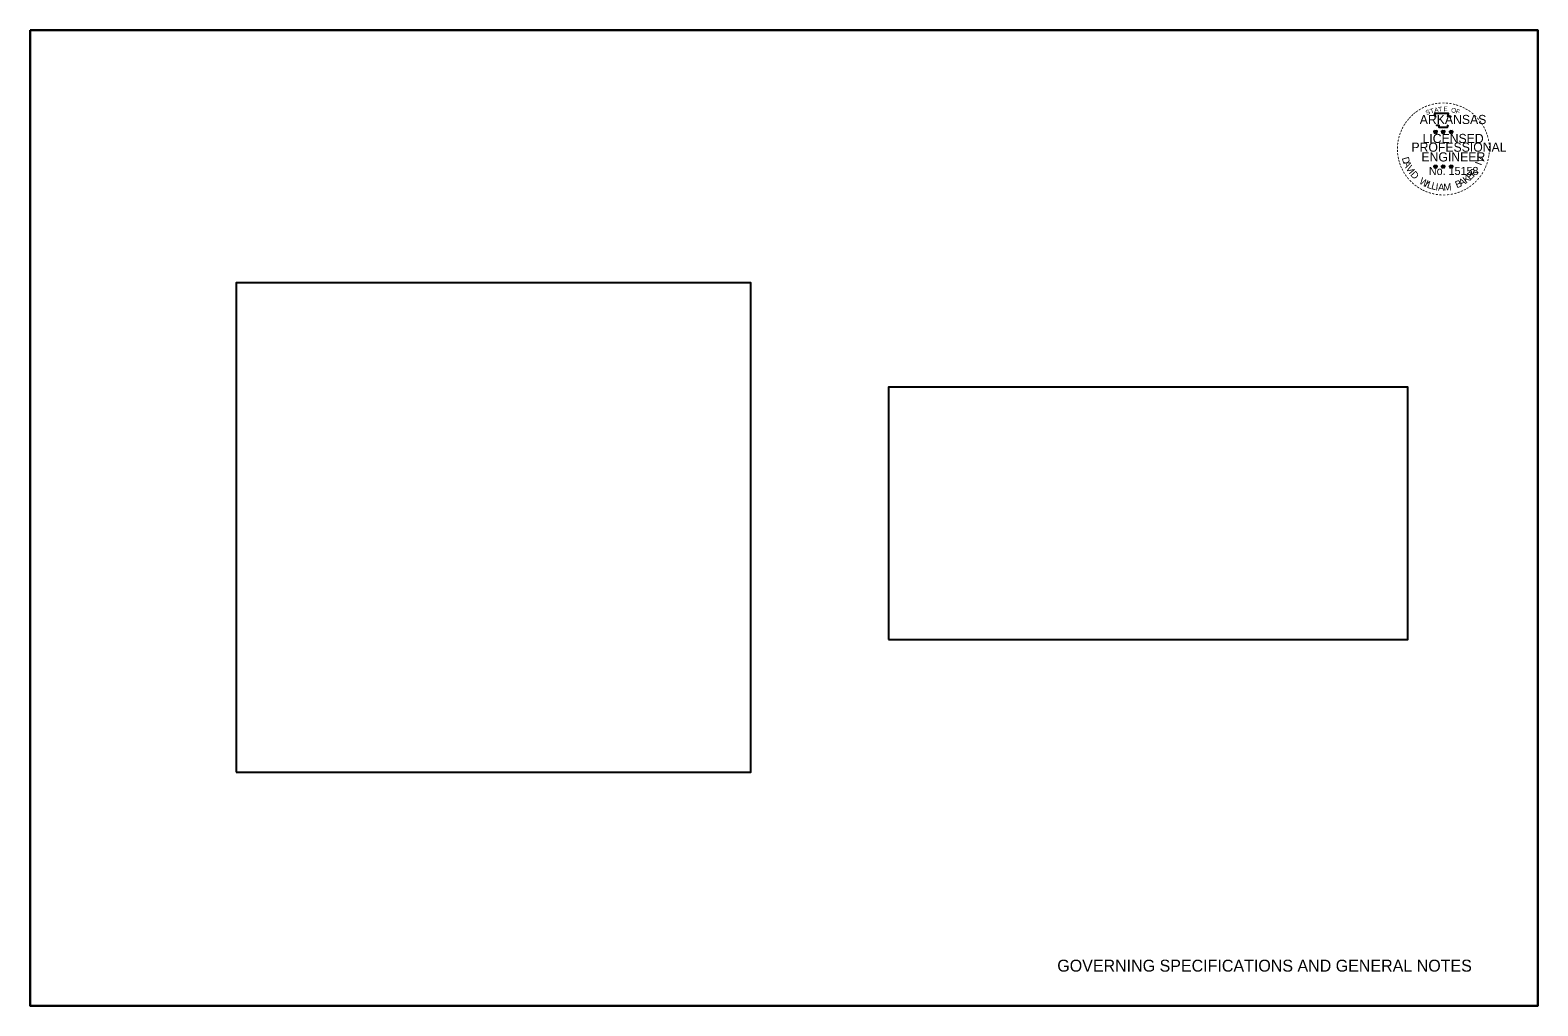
# Model space of a CAD drawing. Extents: x 28704 to 32542, y 50360 to 59122.
# Drawn here: x 28704 to 30404, y 55472 to 56572 of the extents above; entities that cross this region are included whole.
import ezdxf

# ---------------------------------------------------------------- set-up
doc = ezdxf.new("R2010")
doc.units = 0
for name, color, linetype in [('Default', 7, 'Continuous'), ('E_Existing ROW', 7, 'Continuous'), ('R_Border Prem', 7, 'Continuous')]:
    doc.layers.add(name, color=color, linetype=linetype)

msp = doc.modelspace()

# ---------------------------------------------------------------- linework, layer by layer
at = {"layer": 'Default'}
for points in [[(28704, 56572.4), (30404, 56572.4), (30404, 55472.4), (28704, 55472.4)], [(28704, 56572.4), (28704, 55472.4), (30404, 55472.4), (30404, 56572.4)], [(28936.2, 55735.9), (29516.5, 55735.9), (29516.5, 56287.6), (28936.2, 56287.6)], [(29671.6, 55885.4), (30257.3, 55885.4), (30257.3, 56169.8), (29671.6, 56169.8)]]:
    msp.add_lwpolyline(points, close=True, dxfattribs=at)
at = {"layer": 'R_Border Prem'}
for p, q in [((30286.8, 56458.3), (30288.6, 56457.7)), ((30286.8, 56458.3), (30288.1, 56458)), ((30286.8, 56458.3), (30288.1, 56457.6)), ((30287.5, 56456.2), (30288.6, 56457.7)), ((30287.5, 56456.2), (30288.2, 56457.4)), ((30287.5, 56456.2), (30288.6, 56457.3)), ((30288.6, 56459.6), (30288.4, 56458.3)), ((30288.6, 56457.7), (30288.6, 56459.6)), ((30288.6, 56459.6), (30288.9, 56458.3)), ((30290.4, 56458.3), (30288.6, 56457.7)), ((30289.7, 56456.2), (30288.6, 56457.7)), ((30289.7, 56456.2), (30288.6, 56457.3)), ((30290.4, 56458.3), (30288.9, 56458)), ((30289.7, 56456.2), (30289, 56457.7)), ((30290.4, 56458.3), (30289.4, 56457.7)), ((30295.4, 56458.3), (30297.2, 56457.7)), ((30295.4, 56458.3), (30296.8, 56458)), ((30295.4, 56458.3), (30296.7, 56457.6)), ((30296.1, 56456.2), (30297.2, 56457.7)), ((30296.1, 56456.2), (30296.8, 56457.4)), ((30296.1, 56456.2), (30297.2, 56457.3)), ((30297.2, 56459.6), (30297, 56458.3)), ((30297.2, 56457.7), (30297.2, 56459.6)), ((30297.2, 56459.6), (30297.5, 56458.3)), ((30299, 56458.3), (30297.2, 56457.7)), ((30298.3, 56456.2), (30297.2, 56457.7)), ((30298.3, 56456.2), (30297.2, 56457.3)), ((30299, 56458.3), (30297.6, 56458)), ((30298.3, 56456.2), (30297.6, 56457.7)), ((30299, 56458.3), (30298, 56457.7)), ((30304.5, 56458.2), (30306.3, 56457.6)), ((30304.5, 56458.2), (30305.8, 56458)), ((30304.5, 56458.2), (30305.8, 56457.6)), ((30305.2, 56456.1), (30306.3, 56457.6)), ((30305.2, 56456.1), (30305.9, 56457.4)), ((30305.2, 56456.1), (30306.3, 56457.2)), ((30306.3, 56459.5), (30306.1, 56458.2)), ((30306.3, 56457.6), (30306.3, 56459.5)), ((30306.3, 56459.5), (30306.6, 56458.2)), ((30308.1, 56458.2), (30306.3, 56457.6)), ((30307.4, 56456.1), (30306.3, 56457.6)), ((30307.4, 56456.1), (30306.3, 56457.2)), ((30308.1, 56458.2), (30306.7, 56458)), ((30307.4, 56456.1), (30306.7, 56457.6)), ((30308.1, 56458.2), (30307.1, 56457.7)), ((30286.8, 56419.2), (30288.6, 56418.6)), ((30286.8, 56419.2), (30288.1, 56419)), ((30286.8, 56419.2), (30288, 56418.6)), ((30287.5, 56417.1), (30288.6, 56418.6)), ((30287.5, 56417.1), (30288.2, 56418.4)), ((30287.5, 56417.1), (30288.6, 56418.2)), ((30288.6, 56420.5), (30288.4, 56419.2)), ((30288.6, 56418.6), (30288.6, 56420.5)), ((30288.6, 56420.5), (30288.9, 56419.2)), ((30290.4, 56419.2), (30288.6, 56418.6)), ((30289.7, 56417.1), (30288.6, 56418.6)), ((30289.7, 56417.1), (30288.6, 56418.2)), ((30290.4, 56419.2), (30288.9, 56419)), ((30289.7, 56417.1), (30289, 56418.6)), ((30290.4, 56419.2), (30289.4, 56418.7)), ((30295.4, 56419.2), (30297.2, 56418.6)), ((30295.4, 56419.2), (30296.7, 56419)), ((30295.4, 56419.2), (30296.6, 56418.6)), ((30296.1, 56417.1), (30297.2, 56418.6)), ((30296.1, 56417.1), (30296.8, 56418.4)), ((30296.1, 56417.1), (30297.2, 56418.2)), ((30297.2, 56420.5), (30297, 56419.2)), ((30297.2, 56418.6), (30297.2, 56420.5)), ((30297.2, 56420.5), (30297.5, 56419.2)), ((30299, 56419.2), (30297.2, 56418.6)), ((30298.3, 56417.1), (30297.2, 56418.6)), ((30298.3, 56417.1), (30297.2, 56418.2)), ((30299, 56419.2), (30297.5, 56419)), ((30298.3, 56417.1), (30297.6, 56418.6)), ((30299, 56419.2), (30298, 56418.7)), ((30304.5, 56419.2), (30306.3, 56418.6)), ((30304.5, 56419.2), (30305.8, 56418.9)), ((30304.5, 56419.2), (30305.8, 56418.5)), ((30305.2, 56417.1), (30306.3, 56418.6)), ((30305.2, 56417.1), (30305.9, 56418.3)), ((30305.2, 56417.1), (30306.3, 56418.2)), ((30306.3, 56420.5), (30306.1, 56419.2)), ((30306.3, 56418.6), (30306.3, 56420.5)), ((30306.3, 56420.5), (30306.6, 56419.2)), ((30308.1, 56419.2), (30306.3, 56418.6)), ((30307.4, 56417.1), (30306.3, 56418.6)), ((30307.4, 56417.1), (30306.3, 56418.2)), ((30308.1, 56419.2), (30306.6, 56418.9)), ((30307.4, 56417.1), (30306.7, 56418.6)), ((30308.1, 56419.2), (30307.1, 56418.6))]:
    msp.add_line(p, q, dxfattribs=at)
for points in [[(30287, 56478.3), (30288.4, 56474)], [(30305.2, 56473.5), (30305.9, 56475), (30302.4, 56474.9), (30303.1, 56478.3), (30287, 56478.3)], [(30288.6, 56459.6), (30289.7, 56456.2), (30286.8, 56458.3), (30290.4, 56458.3), (30287.5, 56456.2), (30288.6, 56459.6)], [(30289.6, 56465.8), (30289.6, 56465.3), (30292.5, 56465.2), (30292.2, 56462.8), (30301.9, 56462.8), (30302.9, 56465.5)], [(30297.2, 56459.6), (30298.3, 56456.2), (30295.4, 56458.3), (30299, 56458.3), (30296.1, 56456.2), (30297.2, 56459.6)], [(30306.3, 56459.5), (30307.4, 56456.1), (30304.5, 56458.2), (30308.1, 56458.2), (30305.2, 56456.1), (30306.3, 56459.5)], [(30288.6, 56420.5), (30289.7, 56417.1), (30286.8, 56419.2), (30290.4, 56419.2), (30287.5, 56417.1), (30288.6, 56420.5)], [(30297.2, 56420.5), (30298.3, 56417.1), (30295.4, 56419.2), (30299, 56419.2), (30296.1, 56417.1), (30297.2, 56420.5)], [(30306.3, 56420.5), (30307.4, 56417.1), (30304.5, 56419.2), (30308.1, 56419.2), (30305.2, 56417.1), (30306.3, 56420.5)]]:
    msp.add_lwpolyline(points, dxfattribs=at)
for centre, radius in [((30288.6, 56457.7), 0.888), ((30288.6, 56457.7), 0.745), ((30288.6, 56457.7), 0.597), ((30288.6, 56457.7), 0.511), ((30288.6, 56457.7), 0.385), ((30288.6, 56457.7), 0.255), ((30288.6, 56457.7), 0.153), ((30297.2, 56457.7), 0.888), ((30297.2, 56457.7), 0.745), ((30297.2, 56457.7), 0.597), ((30297.2, 56457.7), 0.511), ((30297.2, 56457.7), 0.385), ((30297.2, 56457.7), 0.255), ((30297.2, 56457.7), 0.153), ((30306.3, 56457.6), 0.888), ((30306.3, 56457.6), 0.745), ((30306.3, 56457.6), 0.597), ((30306.3, 56457.6), 0.511), ((30306.3, 56457.6), 0.385), ((30306.3, 56457.6), 0.255), ((30306.3, 56457.6), 0.153), ((30288.6, 56418.6), 0.888), ((30288.6, 56418.6), 0.745), ((30288.6, 56418.6), 0.597), ((30288.6, 56418.6), 0.511), ((30288.6, 56418.6), 0.385), ((30288.6, 56418.6), 0.255), ((30288.6, 56418.6), 0.153), ((30297.2, 56418.6), 0.888), ((30297.2, 56418.6), 0.745), ((30297.2, 56418.6), 0.597), ((30297.2, 56418.6), 0.511), ((30297.2, 56418.6), 0.385), ((30297.2, 56418.6), 0.255), ((30297.2, 56418.6), 0.153), ((30306.3, 56418.6), 0.888), ((30306.3, 56418.6), 0.745), ((30306.3, 56418.6), 0.597), ((30306.3, 56418.6), 0.511), ((30306.3, 56418.6), 0.385), ((30306.3, 56418.6), 0.255), ((30306.3, 56418.6), 0.153)]:
    msp.add_circle(centre, radius, dxfattribs=at)

# ---------------------------------------------------------------- texts
at = {"layer": 'E_Existing ROW'}
msp.add_text('GOVERNING SPECIFICATIONS AND GENERAL NOTES', height=13.5, dxfattribs=at).set_placement((29862.1, 55510.9))
at = {"layer": 'R_Border Prem'}
for s, height, rotation, p in [('-', 8.25, 48.4231, (30261, 56470.5)), ('-', 8.25, 42.9622, (30263.3, 56473)), ('-', 8.25, 38.9507, (30265.5, 56475.2)), ('-', 8.25, 36.2317, (30268, 56477.1)), ('-', 8.25, 34.0636, (30271, 56479.1)), ('-', 8.25, 28.7918, (30274.1, 56481.1)), ('-', 8.25, 24.3072, (30277.3, 56482.7)), ('S', 5.16, 21.594, (30278.6, 56476.6)), ('-', 8.25, 19.1761, (30280.6, 56484.1)), ('T', 5.16, 16.4036, (30283.3, 56478.3)), ('-', 8.25, 13.6302, (30284.5, 56485.3)), ('A', 5.16, 11.2132, (30287.5, 56479.6)), ('-', 8.25, 10.2193, (30288, 56486.2)), ('T', 5.16, 6.0228, (30291.9, 56480.5)), ('-', 8.25, 5.8968, (30291.7, 56486.7)), ('-', 8.25, 0.1862, (30295.7, 56487.1)), ('E', 5.16, 0.8323, (30297.6, 56481)), ('-', 8.25, 357.743, (30299.4, 56487)), ('-', 8.25, 352.1617, (30303.3, 56486.7)), ('O', 5.16, 350.4515, (30305.9, 56479.9)), ('-', 8.25, 347.2049, (30307, 56486.1)), ('F', 5.16, 340.0707, (30310.8, 56478.8)), ('-', 8.25, 342.3362, (30310.2, 56485.3)), ('-', 8.25, 337.8551, (30314, 56484.2)), ('-', 8.25, 334.1211, (30317.3, 56482.8)), ('-', 8.25, 329.6409, (30320.3, 56481.3)), ('-', 8.25, 325.8627, (30323.6, 56479.5)), ('-', 8.25, 320.5297, (30326.7, 56477.3)), ('-', 8.25, 315.5786, (30329.8, 56474.8)), ('-', 8.25, 67.7743, (30252.2, 56456.1)), ('-', 8.25, 62.8713, (30253.5, 56459.2)), ('-', 8.25, 58.0706, (30255.1, 56462.4)), ('-', 8.25, 54.2325, (30256.8, 56465.1)), ('-', 8.25, 50.6142, (30258.9, 56468)), ('-', 8.25, 309.8797, (30332.8, 56471.9)), ('-', 8.25, 306.6522, (30335.5, 56468.8)), ('-', 7.22, 303.6753, (30338, 56465.9)), ('-', 8.25, 299.6684, (30339.6, 56462.8)), ('-', 8.25, 294.6628, (30341.3, 56459.6)), ('-', 8.25, 290.5728, (30342.6, 56456.6)), ('-', 8.25, 89.0622, (30248.8, 56438.3)), ('-', 8.25, 85.1863, (30249, 56441.9)), ('-', 8.25, 81.2013, (30249.3, 56445.5)), ('-', 8.25, 75.461, (30250, 56449.2)), ('-', 8.25, 72.3945, (30251, 56452.8)), ('-', 8.25, 285.1233, (30343.8, 56453.6)), ('-', 8.25, 280.5493, (30344.8, 56449.8)), ('-', 8.25, 276.5962, (30345.7, 56445.9)), ('-', 8.25, 274.3301, (30346, 56442.1)), ('-', 8.25, 94.1959, (30249, 56434.6)), ('-', 8.25, 98.9479, (30249.4, 56431.1)), ('-', 8.25, 101.7149, (30250.1, 56427.3)), ('-', 8.25, 105.4578, (30250.9, 56424.3)), ('-', 8.25, 109.0874, (30252, 56421)), ('D', 7.94, 286.2848, (30250.5, 56428.1)), ('A', 7.94, 292.7835, (30252, 56422.9)), ('I', 7.94, 69.0301, (30340.1, 56419.3)), ('V', 7.94, 72.6573, (30341.2, 56422.1)), ('-', 8.25, 252.8681, (30344.2, 56424.9)), ('-', 8.25, 255.7626, (30345.1, 56428.6)), ('-', 8.25, 260.9953, (30345.7, 56432.1)), ('-', 8.25, 263.5172, (30346.1, 56435.4)), ('-', 8.25, 269.9407, (30346.2, 56438.9)), ('-', 8.25, 114.0643, (30253.3, 56417.9)), ('-', 8.25, 115.7289, (30254.9, 56414.8)), ('-', 8.25, 120.4471, (30256.7, 56411.7)), ('-', 8.25, 125.8934, (30258.8, 56408.8)), ('V', 7.94, 300.7936, (30254.7, 56416.8)), ('-', 8.25, 130.7181, (30261.2, 56406)), ('I', 7.94, 308.3502, (30257.9, 56411.5)), ('D', 7.94, 311.9774, (30259.7, 56409.1)), ('W', 7.94, 328.0731, (30269.4, 56400)), ('K', 7.94, 36.9143, (30323.1, 56399.2)), ('E', 7.94, 44.0175, (30327.8, 56402.8)), ('R', 7.94, 50.3651, (30331.6, 56406.5)), (',', 7.94, 57.4684, (30335.3, 56411)), ('-', 8.25, 233.8452, (30337.6, 56410.9)), ('-', 8.25, 239.0712, (30339.7, 56414.3)), ('-', 8.25, 244.6197, (30341.7, 56418.2)), ('-', 8.25, 247.8887, (30343, 56421.4)), ('-', 8.25, 134.2238, (30263.9, 56403.2)), ('-', 8.25, 138.9338, (30266.6, 56400.8)), ('-', 8.25, 144.6463, (30269.4, 56398.7)), ('-', 8.25, 148.0898, (30272.3, 56396.8)), ('-', 8.25, 151.5704, (30275.3, 56395.1)), ('-', 8.25, 154.6002, (30278, 56393.8)), ('I', 7.94, 336.6877, (30275.6, 56396.3)), ('-', 8.25, 158.5612, (30281.2, 56392.5)), ('L', 7.94, 340.3149, (30278.3, 56395)), ('-', 8.25, 162.7983, (30284.8, 56391.4)), ('L', 7.94, 346.6625, (30283.2, 56393.3)), ('I', 7.94, 353.0101, (30288.3, 56392)), ('A', 7.94, 356.6373, (30291.3, 56391.6)), ('M', 7.94, 4.6473, (30297.9, 56391.3)), ('-', 8.25, 195.4743, (30311.9, 56391.9)), ('B', 7.94, 22.8589, (30312.7, 56394)), ('-', 8.25, 199.4643, (30315.3, 56393.2)), ('A', 7.94, 28.9042, (30317.3, 56396)), ('-', 8.25, 204.2516, (30318.5, 56394.6)), ('-', 8.25, 207.3568, (30321.8, 56396.2)), ('-', 8.25, 212.2491, (30324.6, 56398)), ('-', 8.25, 215.7363, (30327.4, 56400)), ('-', 8.25, 221.0851, (30330.2, 56402.5)), ('-', 8.25, 225.7653, (30332.9, 56405.1)), ('-', 8.25, 231.2538, (30335.4, 56408)), ('-', 8.25, 167.5555, (30288.5, 56390.6)), ('-', 8.25, 173.1155, (30292.4, 56390)), ('-', 8.25, 176.5183, (30296.3, 56389.7)), ('-', 8.25, 181.5918, (30300.1, 56389.8)), ('-', 8.25, 185.8167, (30304.3, 56390.2)), ('-', 8.25, 191.2858, (30308.1, 56390.9))]:
    msp.add_text(s, height=height, rotation=rotation, dxfattribs=at).set_placement(p)
for s, height, p in [('ARKANSAS', 10.31, (30270.8, 56466.5)), ('PROFESSIONAL', 10.312, (30261.4, 56435.3)), ('LICENSED', 10.31, (30273.9, 56445.1)), ('ENGINEER', 10.31, (30272.7, 56424.3)), ('No. 15158', 9.06, (30281.1, 56409.1)), ('AAMU', 0.000103, (30296.9, 56391.3))]:
    msp.add_text(s, height=height, dxfattribs=at).set_placement(p)

doc.saveas('drawing.dxf')
